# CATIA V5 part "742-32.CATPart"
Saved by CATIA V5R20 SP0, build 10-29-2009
Part number: 742-32
Bounding box of the stored display mesh (mm): x -28 to 28.5, y -28 to 28, z -30 to 63
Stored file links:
  C:\Users\Utente\Desktop\IO LAVORO\3D X SITO CF\X SITO\742\742-32.CATPart
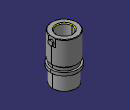
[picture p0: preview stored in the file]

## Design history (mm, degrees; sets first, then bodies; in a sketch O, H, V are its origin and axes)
Set1
  DatumSurface1 to DatumSurface38 "742-32"
Body1 (main body)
